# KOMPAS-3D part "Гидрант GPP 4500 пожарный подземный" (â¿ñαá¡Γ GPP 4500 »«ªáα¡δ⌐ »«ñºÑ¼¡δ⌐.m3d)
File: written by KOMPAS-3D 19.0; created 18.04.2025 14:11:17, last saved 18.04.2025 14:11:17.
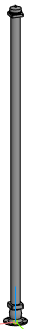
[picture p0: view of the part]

Document properties: Полное имя файла: E:\Dendor Работа Сачек\3D для проекитирвщиков\11.1 Тип GPP. Гидрант пожарный подземный\stp_Тип GPP. 750-6000 Гидрант пожарный подземный\Гидрант GPP 4500 пожарный подземный.m3d

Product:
- Part/product: Гидрант GPP 4500 пожарный подземный

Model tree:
1. Операция без истории:1  (labels: Гидрант GPP 4500 пожарный подземный)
